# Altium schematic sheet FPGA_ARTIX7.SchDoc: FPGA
size C; Organization: Altium Limited; Address1: L3, 12a Rodborough Rd; Address2: Frenchs Forest; Address3: NSW; Address4: Australia 2086; DocumentNumber: 7; SheetNumber: 6; SheetTotal: 12
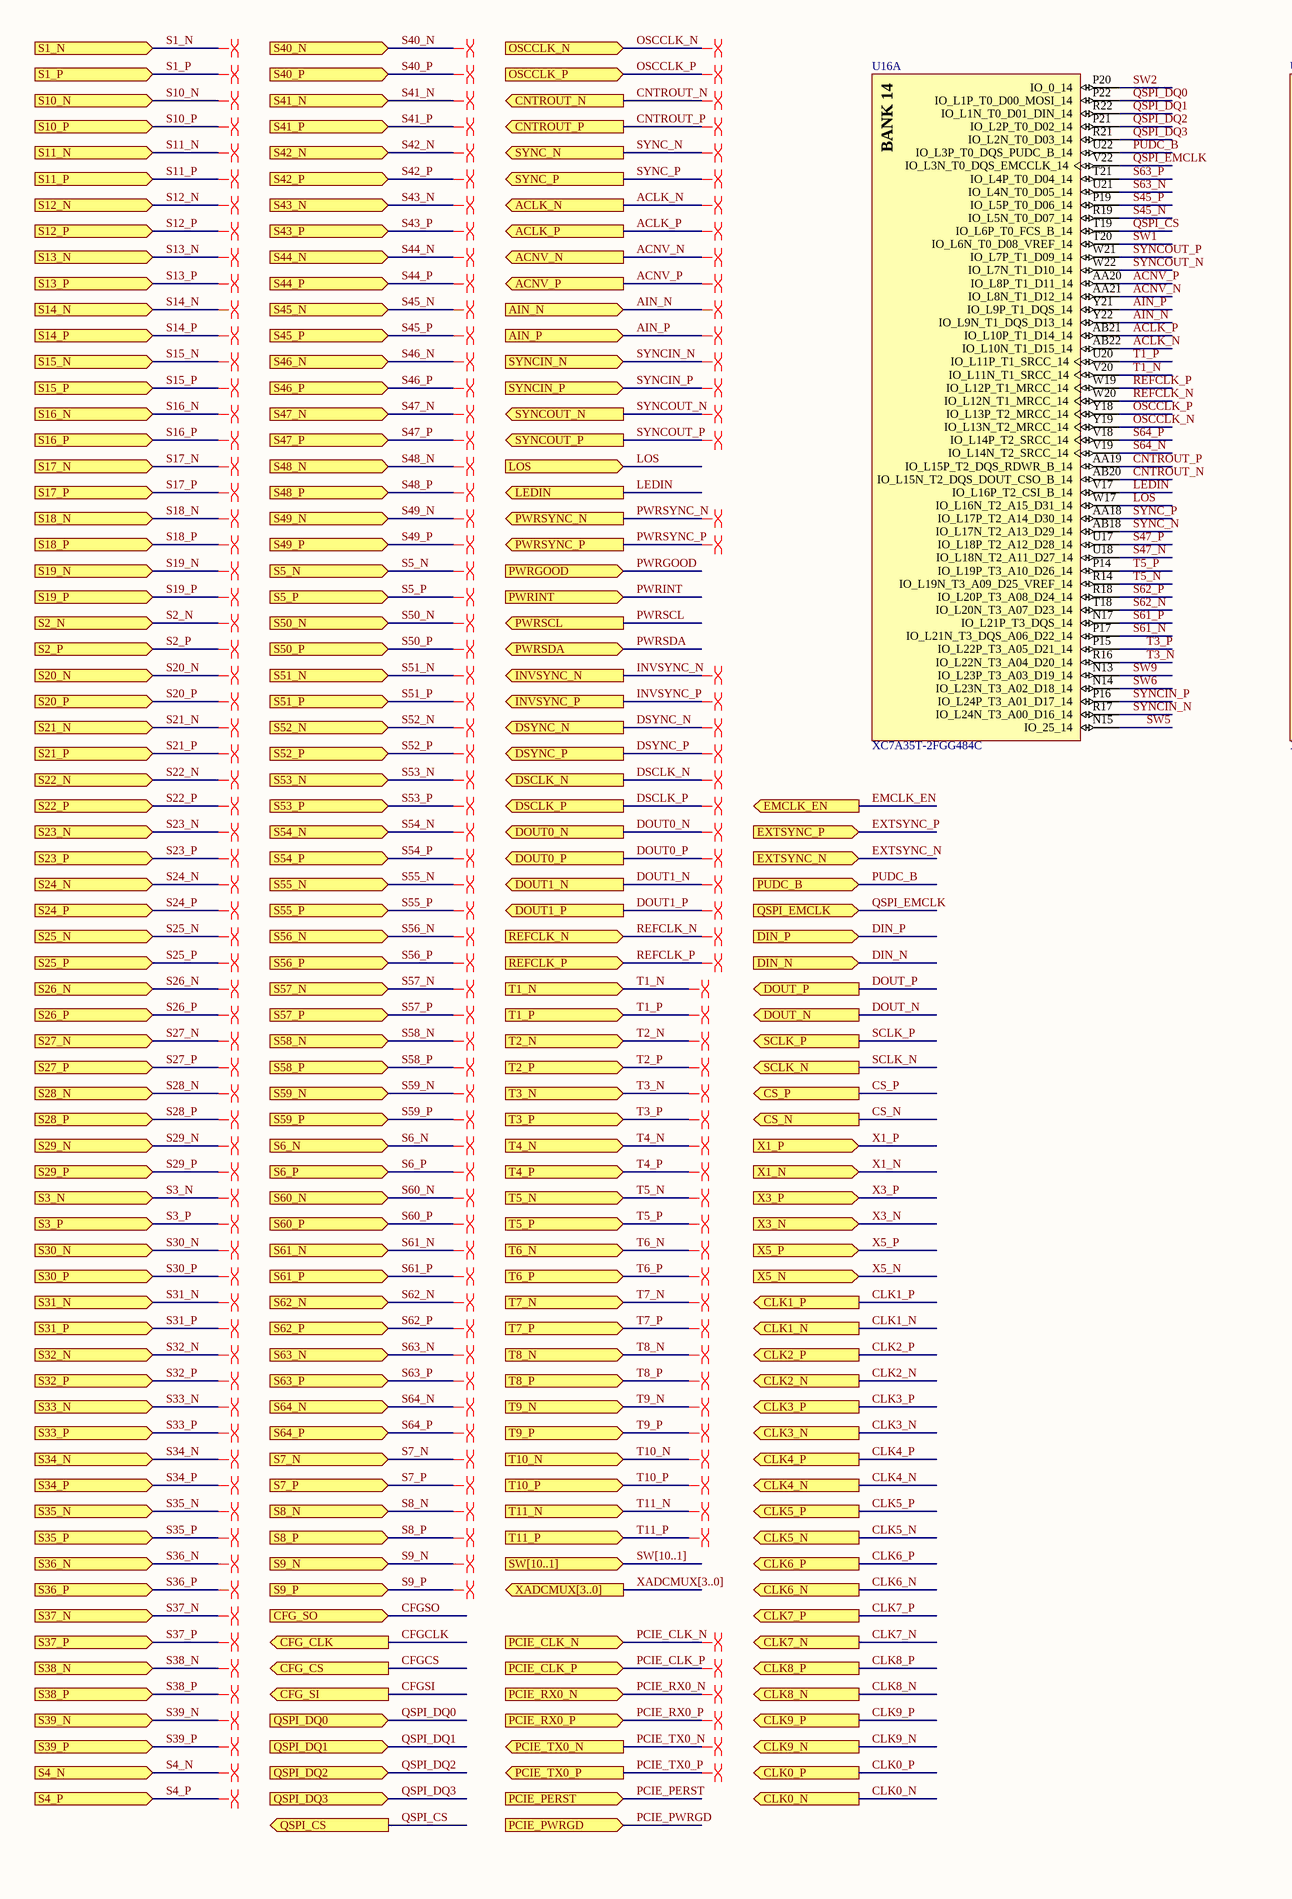
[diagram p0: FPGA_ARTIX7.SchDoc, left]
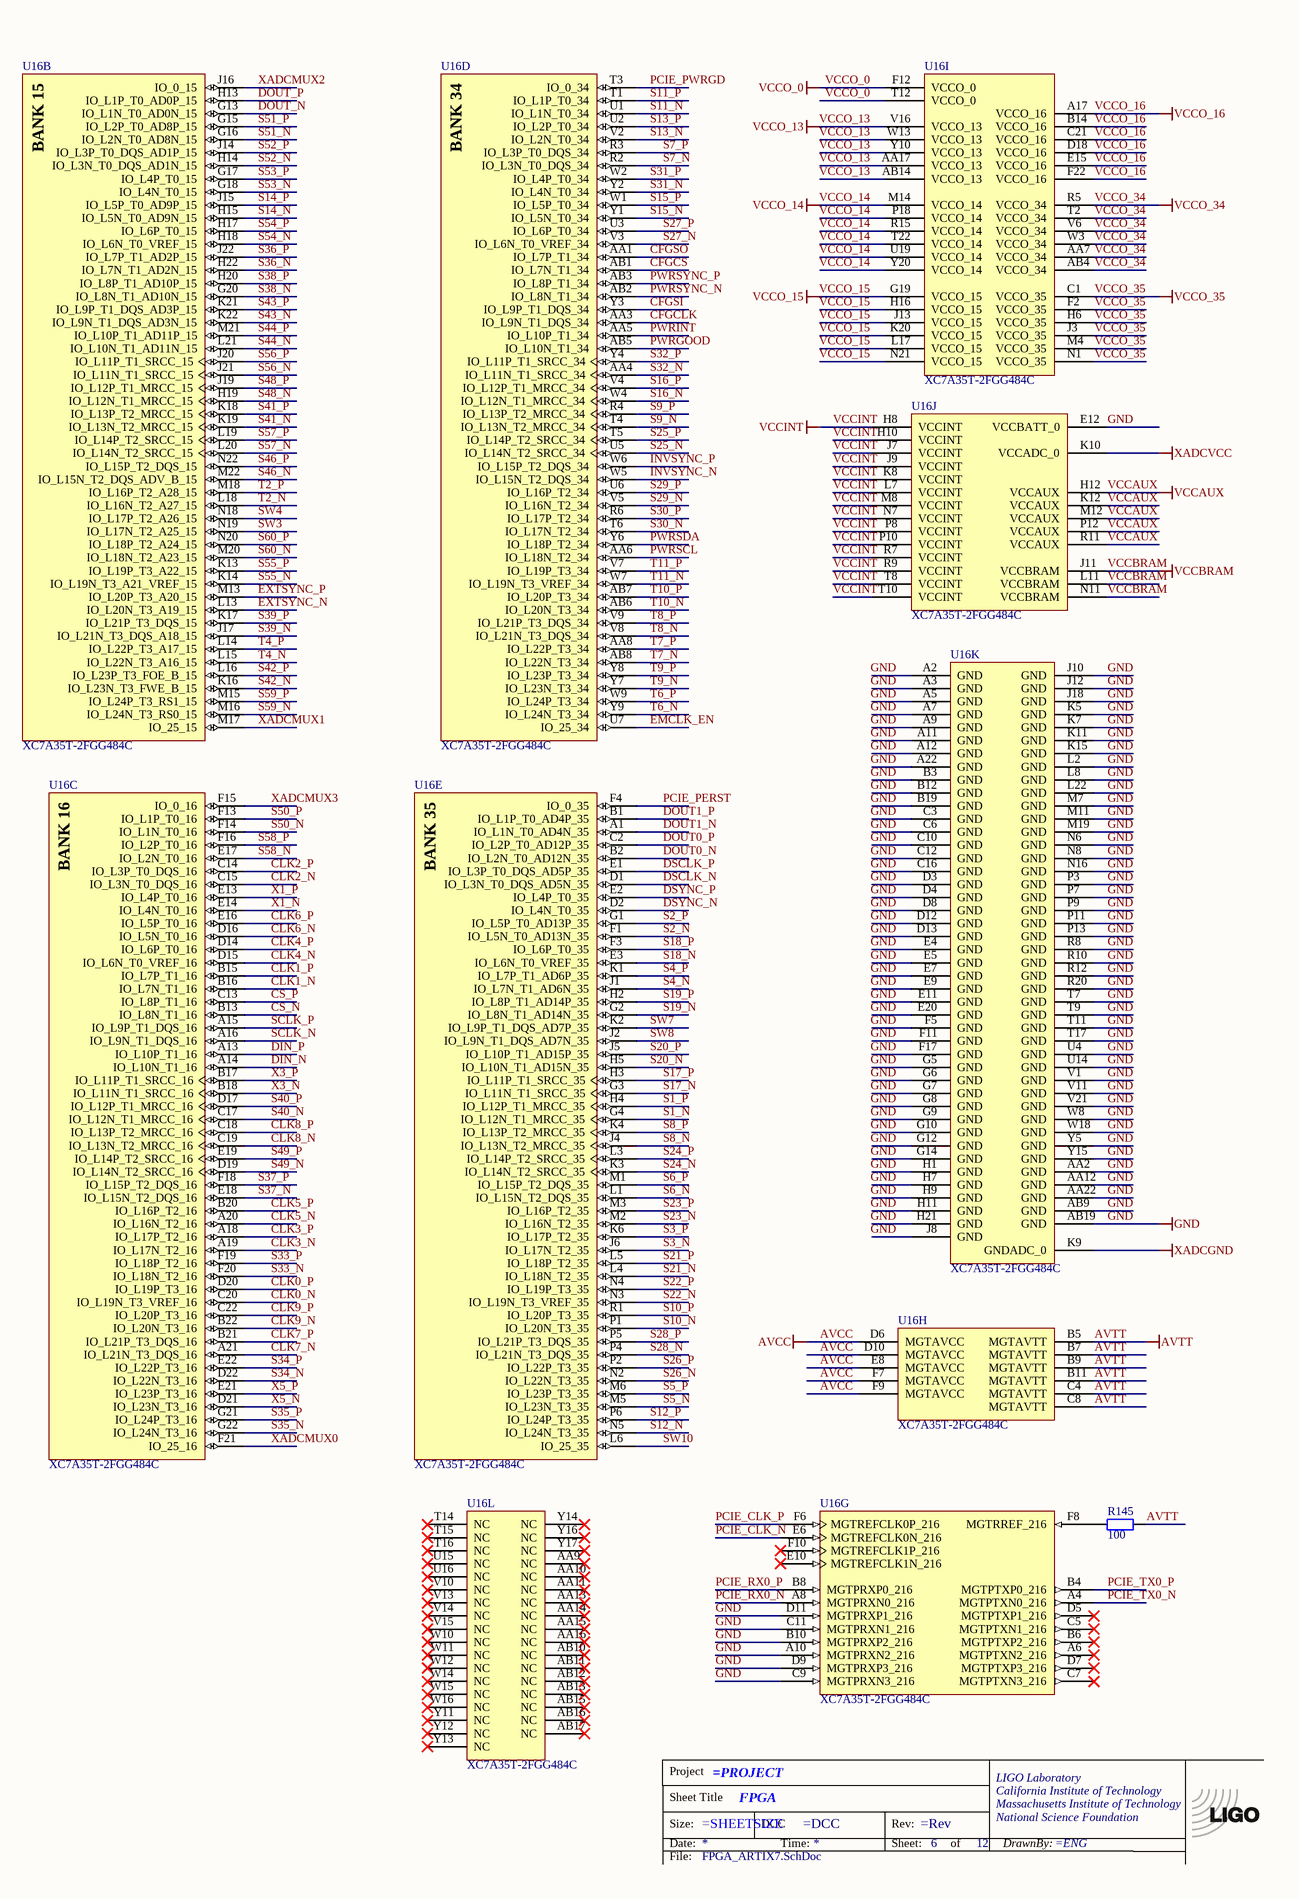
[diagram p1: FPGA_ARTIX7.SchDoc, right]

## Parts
*?  TitleBlock  (value not drawn)  (graphical)
R145  100  [CR1608-0603]
U16  XC7A35T-2FGG484C  [FGG484]  (parts A,B,C,D,E,G,H,I,J,K,L of 12)

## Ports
ACLK_N (out), ACLK_P (out), ACNV_N (out), ACNV_P (out), AIN_N (in), AIN_P (in), CFG_CLK (out), CFG_CS (out), CFG_SI (out), CFG_SO (in), CLK0_N (out), CLK0_P (out), CLK1_N (out), CLK1_P (out), CLK2_N (out), CLK2_P (out), CLK3_N (out), CLK3_P (out), CLK4_N (out), CLK4_P (out), CLK5_N (out), CLK5_P (out), CLK6_N (out), CLK6_P (out), CLK7_N (out), CLK7_P (out), CLK8_N (out), CLK8_P (out), CLK9_N (out), CLK9_P (out), CNTROUT_N (out), CNTROUT_P (out), CS_N (out), CS_P (out), DIN_N (in), DIN_P (in), DOUT0_N (out), DOUT0_P (out), DOUT1_N (out), DOUT1_P (out), DOUT_N (out), DOUT_P (out), DSCLK_N (out), DSCLK_P (out), DSYNC_N (out), DSYNC_P (out), EMCLK_EN (out), EXTSYNC_N (in), EXTSYNC_P (in), INVSYNC_N (out), INVSYNC_P (out), LEDIN (out), LOS (in), OSCCLK_N (in), OSCCLK_P (in), PCIE_CLK_N (in), PCIE_CLK_P (in), PCIE_PERST (in), PCIE_PWRGD (in), PCIE_RX0_N (in), PCIE_RX0_P (in), PCIE_TX0_N (out), PCIE_TX0_P (out), PUDC_B (in), PWRGOOD (in), PWRINT (in), PWRSCL (out), PWRSDA (bidir), PWRSYNC_N (out), PWRSYNC_P (out), QSPI_CS (out), QSPI_DQ0 (in), QSPI_DQ1 (in), QSPI_DQ2 (in), QSPI_DQ3 (in), QSPI_EMCLK (in), REFCLK_N (in), REFCLK_P (in), S1_N (in), S1_P (in), S2_N (in), S2_P (in), S3_N (in), S3_P (in), S4_N (in), S4_P (in), S5_N (in), S5_P (in), S6_N (in), S6_P (in), S7_N (in), S7_P (in), S8_N (in), S8_P (in), S9_N (in), S9_P (in), S10_N (in), S10_P (in), S11_N (in), S11_P (in), S12_N (in), S12_P (in), S13_N (in), S13_P (in), S14_N (in), S14_P (in), S15_N (in), S15_P (in), S16_N (in), S16_P (in), S17_N (in), S17_P (in), S18_N (in), S18_P (in), S19_N (in), S19_P (in), S20_N (in), S20_P (in), S21_N (in), S21_P (in), S22_N (in), S22_P (in), S23_N (in), S23_P (in), S24_N (in), S24_P (in), S25_N (in), S25_P (in), S26_N (in), S26_P (in), S27_N (in), S27_P (in), S28_N (in), S28_P (in), S29_N (in), S29_P (in), S30_N (in), S30_P (in), S31_N (in), S31_P (in), S32_N (in), S32_P (in), S33_N (in), S33_P (in), S34_N (in), S34_P (in), S35_N (in), S35_P (in), S36_N (in), S36_P (in), S37_N (in), S37_P (in), S38_N (in), S38_P (in), S39_N (in), S39_P (in), S40_N (in), S40_P (in), S41_N (in), S41_P (in), S42_N (in), S42_P (in), S43_N (in), S43_P (in), S44_N (in), S44_P (in), S45_N (in), S45_P (in), S46_N (in), S46_P (in), S47_N (in), S47_P (in), S48_N (in), S48_P (in), S49_N (in), S49_P (in), S50_N (in), S50_P (in), S51_N (in), S51_P (in), S52_N (in), S52_P (in), S53_N (in), S53_P (in), S54_N (in), S54_P (in), S55_N (in), S55_P (in), S56_N (in), S56_P (in), S57_N (in), S57_P (in), S58_N (in), S58_P (in), S59_N (in), S59_P (in), S60_N (in), S60_P (in), S61_N (in), S61_P (in), S62_N (in), S62_P (in), S63_N (in), S63_P (in), S64_N (in), S64_P (in), SCLK_N (out), SCLK_P (out), SW[10..1] (in), SYNC_N (out), SYNC_P (out), SYNCIN_N (in), SYNCIN_P (in), SYNCOUT_N (out), SYNCOUT_P (out), T1_N (in), T1_P (in), T2_N (in), T2_P (in), T3_N (in), T3_P (in), T4_N (in), T4_P (in), T5_N (in), T5_P (in), T6_N (in), T6_P (in), T7_N (in), T7_P (in), T8_N (in), T8_P (in), T9_N (in), T9_P (in), T10_N (in), T10_P (in), T11_N (in), T11_P (in), X1_N (in), X1_P (in), X3_N (in), X3_P (in), X5_N (in), X5_P (in), XADCMUX[3..0] (out)

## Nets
AVCC: U16.D6(MGTAVCC) U16.D10(MGTAVCC) U16.E8(MGTAVCC) U16.F7(MGTAVCC) U16.F9(MGTAVCC)
AVTT: R145.2 U16.B5(MGTAVTT) U16.B7(MGTAVTT) U16.B9(MGTAVTT) U16.B11(MGTAVTT) U16.C4(MGTAVTT) U16.C8(MGTAVTT)
GND: U16.A2(GND) U16.A3(GND) U16.A5(GND) U16.A7(GND) U16.A9(GND) U16.A10(MGTPRXN2_216) U16.A11(GND) U16.A12(GND) U16.A22(GND) U16.AA2(GND) U16.AA12(GND) U16.AA22(GND) U16.AB9(GND) U16.AB19(GND) U16.B3(GND) U16.B10(MGTPRXP2_216) U16.B12(GND) U16.B19(GND) U16.C3(GND) U16.C6(GND) U16.C9(MGTPRXN3_216) U16.C10(GND) U16.C11(MGTPRXN1_216) U16.C12(GND) U16.C16(GND) U16.D3(GND) U16.D4(GND) U16.D8(GND) U16.D9(MGTPRXP3_216) U16.D11(MGTPRXP1_216) U16.D12(GND) U16.D13(GND) U16.E4(GND) U16.E5(GND) U16.E7(GND) U16.E9(GND) U16.E11(GND) U16.E12(VCCBATT_0) U16.E20(GND) U16.F5(GND) U16.F11(GND) U16.F17(GND) U16.G5(GND) U16.G6(GND) U16.G7(GND) U16.G8(GND) U16.G9(GND) U16.G10(GND) U16.G12(GND) U16.G14(GND) U16.H1(GND) U16.H7(GND) U16.H9(GND) U16.H11(GND) U16.H21(GND) U16.J8(GND) U16.J10(GND) U16.J12(GND) U16.J18(GND) U16.K5(GND) U16.K7(GND) U16.K11(GND) U16.K15(GND) U16.L2(GND) U16.L8(GND) U16.L22(GND) U16.M7(GND) U16.M11(GND) U16.M19(GND) U16.N6(GND) U16.N8(GND) U16.N16(GND) U16.P3(GND) U16.P7(GND) U16.P9(GND) U16.P11(GND) U16.P13(GND) U16.R8(GND) U16.R10(GND) U16.R12(GND) U16.R20(GND) U16.T7(GND) U16.T9(GND) U16.T11(GND) U16.T17(GND) U16.U4(GND) U16.U14(GND) U16.V1(GND) U16.V11(GND) U16.V21(GND) U16.W8(GND) U16.W18(GND) U16.Y5(GND) U16.Y15(GND)
VCCAUX: U16.H12(VCCAUX) U16.K12(VCCAUX) U16.M12(VCCAUX) U16.P12(VCCAUX) U16.R11(VCCAUX)
VCCBRAM: U16.J11(VCCBRAM) U16.L11(VCCBRAM) U16.N11(VCCBRAM)
VCCINT: U16.H8(VCCINT) U16.H10(VCCINT) U16.J7(VCCINT) U16.J9(VCCINT) U16.K8(VCCINT) U16.L7(VCCINT) U16.M8(VCCINT) U16.N7(VCCINT) U16.P8(VCCINT) U16.P10(VCCINT) U16.R7(VCCINT) U16.R9(VCCINT) U16.T8(VCCINT) U16.T10(VCCINT)
VCCO_0: U16.F12(VCCO_0) U16.T12(VCCO_0)
VCCO_13: U16.AA17(VCCO_13) U16.AB14(VCCO_13) U16.V16(VCCO_13) U16.W13(VCCO_13) U16.Y10(VCCO_13)
VCCO_14: U16.M14(VCCO_14) U16.P18(VCCO_14) U16.R15(VCCO_14) U16.T22(VCCO_14) U16.U19(VCCO_14) U16.Y20(VCCO_14)
VCCO_15: U16.G19(VCCO_15) U16.H16(VCCO_15) U16.J13(VCCO_15) U16.K20(VCCO_15) U16.L17(VCCO_15) U16.N21(VCCO_15)
VCCO_16: U16.A17(VCCO_16) U16.B14(VCCO_16) U16.C21(VCCO_16) U16.D18(VCCO_16) U16.E15(VCCO_16) U16.F22(VCCO_16)
VCCO_34: U16.AA7(VCCO_34) U16.AB4(VCCO_34) U16.R5(VCCO_34) U16.T2(VCCO_34) U16.V6(VCCO_34) U16.W3(VCCO_34)
VCCO_35: U16.C1(VCCO_35) U16.F2(VCCO_35) U16.H6(VCCO_35) U16.J3(VCCO_35) U16.M4(VCCO_35) U16.N1(VCCO_35)
XADCGND: U16.K9(GNDADC_0)
XADCVCC: U16.K10(VCCADC_0)
ACLK_N: U16.AB22(IO_L10N_T1_D15_14) ; port ACLK_N
ACLK_P: U16.AB21(IO_L10P_T1_D14_14) ; port ACLK_P
ACNV_N: U16.AA21(IO_L8N_T1_D12_14) ; port ACNV_N
ACNV_P: U16.AA20(IO_L8P_T1_D11_14) ; port ACNV_P
AIN_N: U16.Y22(IO_L9N_T1_DQS_D13_14) ; port AIN_N
AIN_P: U16.Y21(IO_L9P_T1_DQS_14) ; port AIN_P
CFGCLK: U16.AA3(IO_L9N_T1_DQS_34) ; port CFG_CLK
CFGCS: U16.AB1(IO_L7N_T1_34) ; port CFG_CS
CFGSI: U16.Y3(IO_L9P_T1_DQS_34) ; port CFG_SI
CFGSO: U16.AA1(IO_L7P_T1_34) ; port CFG_SO
CLK0_N: U16.C20(IO_L19N_T3_VREF_16) ; port CLK0_N
CLK0_P: U16.D20(IO_L19P_T3_16) ; port CLK0_P
CLK1_N: U16.B16(IO_L7N_T1_16) ; port CLK1_N
CLK1_P: U16.B15(IO_L7P_T1_16) ; port CLK1_P
CLK2_N: U16.C15(IO_L3N_T0_DQS_16) ; port CLK2_N
CLK2_P: U16.C14(IO_L3P_T0_DQS_16) ; port CLK2_P
CLK3_N: U16.A19(IO_L17N_T2_16) ; port CLK3_N
CLK3_P: U16.A18(IO_L17P_T2_16) ; port CLK3_P
CLK4_N: U16.D15(IO_L6N_T0_VREF_16) ; port CLK4_N
CLK4_P: U16.D14(IO_L6P_T0_16) ; port CLK4_P
CLK5_N: U16.A20(IO_L16N_T2_16) ; port CLK5_N
CLK5_P: U16.B20(IO_L16P_T2_16) ; port CLK5_P
CLK6_N: U16.D16(IO_L5N_T0_16) ; port CLK6_N
CLK6_P: U16.E16(IO_L5P_T0_16) ; port CLK6_P
CLK7_N: U16.A21(IO_L21N_T3_DQS_16) ; port CLK7_N
CLK7_P: U16.B21(IO_L21P_T3_DQS_16) ; port CLK7_P
CLK8_N: U16.C19(IO_L13N_T2_MRCC_16) ; port CLK8_N
CLK8_P: U16.C18(IO_L13P_T2_MRCC_16) ; port CLK8_P
CLK9_N: U16.B22(IO_L20N_T3_16) ; port CLK9_N
CLK9_P: U16.C22(IO_L20P_T3_16) ; port CLK9_P
CNTROUT_N: U16.AB20(IO_L15N_T2_DQS_DOUT_CSO_B_14) ; port CNTROUT_N
CNTROUT_P: U16.AA19(IO_L15P_T2_DQS_RDWR_B_14) ; port CNTROUT_P
CS_N: U16.B13(IO_L8N_T1_16) ; port CS_N
CS_P: U16.C13(IO_L8P_T1_16) ; port CS_P
DIN_N: U16.A14(IO_L10N_T1_16) ; port DIN_N
DIN_P: U16.A13(IO_L10P_T1_16) ; port DIN_P
DOUT0_N: U16.B2(IO_L2N_T0_AD12N_35) ; port DOUT0_N
DOUT0_P: U16.C2(IO_L2P_T0_AD12P_35) ; port DOUT0_P
DOUT1_N: U16.A1(IO_L1N_T0_AD4N_35) ; port DOUT1_N
DOUT1_P: U16.B1(IO_L1P_T0_AD4P_35) ; port DOUT1_P
DOUT_N: U16.G13(IO_L1N_T0_AD0N_15) ; port DOUT_N
DOUT_P: U16.H13(IO_L1P_T0_AD0P_15) ; port DOUT_P
DSCLK_N: U16.D1(IO_L3N_T0_DQS_AD5N_35) ; port DSCLK_N
DSCLK_P: U16.E1(IO_L3P_T0_DQS_AD5P_35) ; port DSCLK_P
DSYNC_N: U16.D2(IO_L4N_T0_35) ; port DSYNC_N
DSYNC_P: U16.E2(IO_L4P_T0_35) ; port DSYNC_P
EMCLK_EN: U16.U7(IO_25_34) ; port EMCLK_EN
EXTSYNC_N: U16.L13(IO_L20N_T3_A19_15) ; port EXTSYNC_N
EXTSYNC_P: U16.M13(IO_L20P_T3_A20_15) ; port EXTSYNC_P
INVSYNC_N: U16.W5(IO_L15N_T2_DQS_34) ; port INVSYNC_N
INVSYNC_P: U16.W6(IO_L15P_T2_DQS_34) ; port INVSYNC_P
LEDIN: U16.V17(IO_L16P_T2_CSI_B_14) ; port LEDIN
LOS: U16.W17(IO_L16N_T2_A15_D31_14) ; port LOS
OSCCLK_N: U16.Y19(IO_L13N_T2_MRCC_14) ; port OSCCLK_N
OSCCLK_P: U16.Y18(IO_L13P_T2_MRCC_14) ; port OSCCLK_P
PCIE_CLK_N: U16.E6(MGTREFCLK0N_216) ; port PCIE_CLK_N
PCIE_CLK_P: U16.F6(MGTREFCLK0P_216) ; port PCIE_CLK_P
PCIE_PERST: U16.F4(IO_0_35) ; port PCIE_PERST
PCIE_PWRGD: U16.T3(IO_0_34) ; port PCIE_PWRGD
PCIE_RX0_N: U16.A8(MGTPRXN0_216) ; port PCIE_RX0_N
PCIE_RX0_P: U16.B8(MGTPRXP0_216) ; port PCIE_RX0_P
PCIE_TX0_N: U16.A4(MGTPTXN0_216) ; port PCIE_TX0_N
PCIE_TX0_P: U16.B4(MGTPTXP0_216) ; port PCIE_TX0_P
PUDC_B: U16.U22(IO_L3P_T0_DQS_PUDC_B_14) ; port PUDC_B
PWRGOOD: U16.AB5(IO_L10N_T1_34) ; port PWRGOOD
PWRINT: U16.AA5(IO_L10P_T1_34) ; port PWRINT
PWRSCL: U16.AA6(IO_L18N_T2_34) ; port PWRSCL
PWRSDA: U16.Y6(IO_L18P_T2_34) ; port PWRSDA
PWRSYNC_N: U16.AB2(IO_L8N_T1_34) ; port PWRSYNC_N
PWRSYNC_P: U16.AB3(IO_L8P_T1_34) ; port PWRSYNC_P
QSPI_CS: U16.T19(IO_L6P_T0_FCS_B_14) ; port QSPI_CS
QSPI_DQ0: U16.P22(IO_L1P_T0_D00_MOSI_14) ; port QSPI_DQ0
QSPI_DQ1: U16.R22(IO_L1N_T0_D01_DIN_14) ; port QSPI_DQ1
QSPI_DQ2: U16.P21(IO_L2P_T0_D02_14) ; port QSPI_DQ2
QSPI_DQ3: U16.R21(IO_L2N_T0_D03_14) ; port QSPI_DQ3
QSPI_EMCLK: U16.V22(IO_L3N_T0_DQS_EMCCLK_14) ; port QSPI_EMCLK
REFCLK_N: U16.W20(IO_L12N_T1_MRCC_14) ; port REFCLK_N
REFCLK_P: U16.W19(IO_L12P_T1_MRCC_14) ; port REFCLK_P
S1_N: U16.G4(IO_L12N_T1_MRCC_35) ; port S1_N
S1_P: U16.H4(IO_L12P_T1_MRCC_35) ; port S1_P
S2_N: U16.F1(IO_L5N_T0_AD13N_35) ; port S2_N
S2_P: U16.G1(IO_L5P_T0_AD13P_35) ; port S2_P
S3_N: U16.J6(IO_L17N_T2_35) ; port S3_N
S3_P: U16.K6(IO_L17P_T2_35) ; port S3_P
S4_N: U16.J1(IO_L7N_T1_AD6N_35) ; port S4_N
S4_P: U16.K1(IO_L7P_T1_AD6P_35) ; port S4_P
S5_N: U16.M5(IO_L23N_T3_35) ; port S5_N
S5_P: U16.M6(IO_L23P_T3_35) ; port S5_P
S6_N: U16.L1(IO_L15N_T2_DQS_35) ; port S6_N
S6_P: U16.M1(IO_L15P_T2_DQS_35) ; port S6_P
S7_N: U16.R2(IO_L3N_T0_DQS_34) ; port S7_N
S7_P: U16.R3(IO_L3P_T0_DQS_34) ; port S7_P
S8_N: U16.J4(IO_L13N_T2_MRCC_35) ; port S8_N
S8_P: U16.K4(IO_L13P_T2_MRCC_35) ; port S8_P
S9_N: U16.T4(IO_L13N_T2_MRCC_34) ; port S9_N
S9_P: U16.R4(IO_L13P_T2_MRCC_34) ; port S9_P
S10_N: U16.P1(IO_L20N_T3_35) ; port S10_N
S10_P: U16.R1(IO_L20P_T3_35) ; port S10_P
S11_N: U16.U1(IO_L1N_T0_34) ; port S11_N
S11_P: U16.T1(IO_L1P_T0_34) ; port S11_P
S12_N: U16.N5(IO_L24N_T3_35) ; port S12_N
S12_P: U16.P6(IO_L24P_T3_35) ; port S12_P
S13_N: U16.V2(IO_L2N_T0_34) ; port S13_N
S13_P: U16.U2(IO_L2P_T0_34) ; port S13_P
S14_N: U16.H15(IO_L5N_T0_AD9N_15) ; port S14_N
S14_P: U16.J15(IO_L5P_T0_AD9P_15) ; port S14_P
S15_N: U16.Y1(IO_L5N_T0_34) ; port S15_N
S15_P: U16.W1(IO_L5P_T0_34) ; port S15_P
S16_N: U16.W4(IO_L12N_T1_MRCC_34) ; port S16_N
S16_P: U16.V4(IO_L12P_T1_MRCC_34) ; port S16_P
S17_N: U16.G3(IO_L11N_T1_SRCC_35) ; port S17_N
S17_P: U16.H3(IO_L11P_T1_SRCC_35) ; port S17_P
S18_N: U16.E3(IO_L6N_T0_VREF_35) ; port S18_N
S18_P: U16.F3(IO_L6P_T0_35) ; port S18_P
S19_N: U16.G2(IO_L8N_T1_AD14N_35) ; port S19_N
S19_P: U16.H2(IO_L8P_T1_AD14P_35) ; port S19_P
S20_N: U16.H5(IO_L10N_T1_AD15N_35) ; port S20_N
S20_P: U16.J5(IO_L10P_T1_AD15P_35) ; port S20_P
S21_N: U16.L4(IO_L18N_T2_35) ; port S21_N
S21_P: U16.L5(IO_L18P_T2_35) ; port S21_P
S22_N: U16.N3(IO_L19N_T3_VREF_35) ; port S22_N
S22_P: U16.N4(IO_L19P_T3_35) ; port S22_P
S23_N: U16.M2(IO_L16N_T2_35) ; port S23_N
S23_P: U16.M3(IO_L16P_T2_35) ; port S23_P
S24_N: U16.K3(IO_L14N_T2_SRCC_35) ; port S24_N
S24_P: U16.L3(IO_L14P_T2_SRCC_35) ; port S24_P
S25_N: U16.U5(IO_L14N_T2_SRCC_34) ; port S25_N
S25_P: U16.T5(IO_L14P_T2_SRCC_34) ; port S25_P
S26_N: U16.N2(IO_L22N_T3_35) ; port S26_N
S26_P: U16.P2(IO_L22P_T3_35) ; port S26_P
S27_N: U16.V3(IO_L6N_T0_VREF_34) ; port S27_N
S27_P: U16.U3(IO_L6P_T0_34) ; port S27_P
S28_N: U16.P4(IO_L21N_T3_DQS_35) ; port S28_N
S28_P: U16.P5(IO_L21P_T3_DQS_35) ; port S28_P
S29_N: U16.V5(IO_L16N_T2_34) ; port S29_N
S29_P: U16.U6(IO_L16P_T2_34) ; port S29_P
S30_N: U16.T6(IO_L17N_T2_34) ; port S30_N
S30_P: U16.R6(IO_L17P_T2_34) ; port S30_P
S31_N: U16.Y2(IO_L4N_T0_34) ; port S31_N
S31_P: U16.W2(IO_L4P_T0_34) ; port S31_P
S32_N: U16.AA4(IO_L11N_T1_SRCC_34) ; port S32_N
S32_P: U16.Y4(IO_L11P_T1_SRCC_34) ; port S32_P
S33_N: U16.F20(IO_L18N_T2_16) ; port S33_N
S33_P: U16.F19(IO_L18P_T2_16) ; port S33_P
S34_N: U16.D22(IO_L22N_T3_16) ; port S34_N
S34_P: U16.E22(IO_L22P_T3_16) ; port S34_P
S35_N: U16.G22(IO_L24N_T3_16) ; port S35_N
S35_P: U16.G21(IO_L24P_T3_16) ; port S35_P
S36_N: U16.H22(IO_L7N_T1_AD2N_15) ; port S36_N
S36_P: U16.J22(IO_L7P_T1_AD2P_15) ; port S36_P
S37_N: U16.E18(IO_L15N_T2_DQS_16) ; port S37_N
S37_P: U16.F18(IO_L15P_T2_DQS_16) ; port S37_P
S38_N: U16.G20(IO_L8N_T1_AD10N_15) ; port S38_N
S38_P: U16.H20(IO_L8P_T1_AD10P_15) ; port S38_P
S39_N: U16.J17(IO_L21N_T3_DQS_A18_15) ; port S39_N
S39_P: U16.K17(IO_L21P_T3_DQS_15) ; port S39_P
S40_N: U16.C17(IO_L12N_T1_MRCC_16) ; port S40_N
S40_P: U16.D17(IO_L12P_T1_MRCC_16) ; port S40_P
S41_N: U16.K19(IO_L13N_T2_MRCC_15) ; port S41_N
S41_P: U16.K18(IO_L13P_T2_MRCC_15) ; port S41_P
S42_N: U16.K16(IO_L23N_T3_FWE_B_15) ; port S42_N
S42_P: U16.L16(IO_L23P_T3_FOE_B_15) ; port S42_P
S43_N: U16.K22(IO_L9N_T1_DQS_AD3N_15) ; port S43_N
S43_P: U16.K21(IO_L9P_T1_DQS_AD3P_15) ; port S43_P
S44_N: U16.L21(IO_L10N_T1_AD11N_15) ; port S44_N
S44_P: U16.M21(IO_L10P_T1_AD11P_15) ; port S44_P
S45_N: U16.R19(IO_L5N_T0_D07_14) ; port S45_N
S45_P: U16.P19(IO_L5P_T0_D06_14) ; port S45_P
S46_N: U16.M22(IO_L15N_T2_DQS_ADV_B_15) ; port S46_N
S46_P: U16.N22(IO_L15P_T2_DQS_15) ; port S46_P
S47_N: U16.U18(IO_L18N_T2_A11_D27_14) ; port S47_N
S47_P: U16.U17(IO_L18P_T2_A12_D28_14) ; port S47_P
S48_N: U16.H19(IO_L12N_T1_MRCC_15) ; port S48_N
S48_P: U16.J19(IO_L12P_T1_MRCC_15) ; port S48_P
S49_N: U16.D19(IO_L14N_T2_SRCC_16) ; port S49_N
S49_P: U16.E19(IO_L14P_T2_SRCC_16) ; port S49_P
S50_N: U16.F14(IO_L1N_T0_16) ; port S50_N
S50_P: U16.F13(IO_L1P_T0_16) ; port S50_P
S51_N: U16.G16(IO_L2N_T0_AD8N_15) ; port S51_N
S51_P: U16.G15(IO_L2P_T0_AD8P_15) ; port S51_P
S52_N: U16.H14(IO_L3N_T0_DQS_AD1N_15) ; port S52_N
S52_P: U16.J14(IO_L3P_T0_DQS_AD1P_15) ; port S52_P
S53_N: U16.G18(IO_L4N_T0_15) ; port S53_N
S53_P: U16.G17(IO_L4P_T0_15) ; port S53_P
S54_N: U16.H18(IO_L6N_T0_VREF_15) ; port S54_N
S54_P: U16.H17(IO_L6P_T0_15) ; port S54_P
S55_N: U16.K14(IO_L19N_T3_A21_VREF_15) ; port S55_N
S55_P: U16.K13(IO_L19P_T3_A22_15) ; port S55_P
S56_N: U16.J21(IO_L11N_T1_SRCC_15) ; port S56_N
S56_P: U16.J20(IO_L11P_T1_SRCC_15) ; port S56_P
S57_N: U16.L20(IO_L14N_T2_SRCC_15) ; port S57_N
S57_P: U16.L19(IO_L14P_T2_SRCC_15) ; port S57_P
S58_N: U16.E17(IO_L2N_T0_16) ; port S58_N
S58_P: U16.F16(IO_L2P_T0_16) ; port S58_P
S59_N: U16.M16(IO_L24N_T3_RS0_15) ; port S59_N
S59_P: U16.M15(IO_L24P_T3_RS1_15) ; port S59_P
S60_N: U16.M20(IO_L18N_T2_A23_15) ; port S60_N
S60_P: U16.N20(IO_L18P_T2_A24_15) ; port S60_P
S61_N: U16.P17(IO_L21N_T3_DQS_A06_D22_14) ; port S61_N
S61_P: U16.N17(IO_L21P_T3_DQS_14) ; port S61_P
S62_N: U16.T18(IO_L20N_T3_A07_D23_14) ; port S62_N
S62_P: U16.R18(IO_L20P_T3_A08_D24_14) ; port S62_P
S63_N: U16.U21(IO_L4N_T0_D05_14) ; port S63_N
S63_P: U16.T21(IO_L4P_T0_D04_14) ; port S63_P
S64_N: U16.V19(IO_L14N_T2_SRCC_14) ; port S64_N
S64_P: U16.V18(IO_L14P_T2_SRCC_14) ; port S64_P
SCLK_N: U16.A16(IO_L9N_T1_DQS_16) ; port SCLK_N
SCLK_P: U16.A15(IO_L9P_T1_DQS_16) ; port SCLK_P
SW1: U16.T20(IO_L6N_T0_D08_VREF_14)
SW2: U16.P20(IO_0_14)
SW3: U16.N19(IO_L17N_T2_A25_15)
SW4: U16.N18(IO_L17P_T2_A26_15)
SW5: U16.N15(IO_25_14)
SW6: U16.N14(IO_L23N_T3_A02_D18_14)
SW7: U16.K2(IO_L9P_T1_DQS_AD7P_35)
SW8: U16.J2(IO_L9N_T1_DQS_AD7N_35)
SW9: U16.N13(IO_L23P_T3_A03_D19_14)
SW10: U16.L6(IO_25_35)
SYNC_N: U16.AB18(IO_L17N_T2_A13_D29_14) ; port SYNC_N
SYNC_P: U16.AA18(IO_L17P_T2_A14_D30_14) ; port SYNC_P
SYNCIN_N: U16.R17(IO_L24N_T3_A00_D16_14) ; port SYNCIN_N
SYNCIN_P: U16.P16(IO_L24P_T3_A01_D17_14) ; port SYNCIN_P
SYNCOUT_N: U16.W22(IO_L7N_T1_D10_14) ; port SYNCOUT_N
SYNCOUT_P: U16.W21(IO_L7P_T1_D09_14) ; port SYNCOUT_P
T1_N: U16.V20(IO_L11N_T1_SRCC_14) ; port T1_N
T1_P: U16.U20(IO_L11P_T1_SRCC_14) ; port T1_P
T2_N: U16.L18(IO_L16N_T2_A27_15) ; port T2_N
T2_P: U16.M18(IO_L16P_T2_A28_15) ; port T2_P
T3_N: U16.R16(IO_L22N_T3_A04_D20_14) ; port T3_N
T3_P: U16.P15(IO_L22P_T3_A05_D21_14) ; port T3_P
T4_N: U16.L15(IO_L22N_T3_A16_15) ; port T4_N
T4_P: U16.L14(IO_L22P_T3_A17_15) ; port T4_P
T5_N: U16.R14(IO_L19N_T3_A09_D25_VREF_14) ; port T5_N
T5_P: U16.P14(IO_L19P_T3_A10_D26_14) ; port T5_P
T6_N: U16.Y9(IO_L24N_T3_34) ; port T6_N
T6_P: U16.W9(IO_L24P_T3_34) ; port T6_P
T7_N: U16.AB8(IO_L22N_T3_34) ; port T7_N
T7_P: U16.AA8(IO_L22P_T3_34) ; port T7_P
T8_N: U16.V8(IO_L21N_T3_DQS_34) ; port T8_N
T8_P: U16.V9(IO_L21P_T3_DQS_34) ; port T8_P
T9_N: U16.Y7(IO_L23N_T3_34) ; port T9_N
T9_P: U16.Y8(IO_L23P_T3_34) ; port T9_P
T10_N: U16.AB6(IO_L20N_T3_34) ; port T10_N
T10_P: U16.AB7(IO_L20P_T3_34) ; port T10_P
T11_N: U16.W7(IO_L19N_T3_VREF_34) ; port T11_N
T11_P: U16.V7(IO_L19P_T3_34) ; port T11_P
X1_N: U16.E14(IO_L4N_T0_16) ; port X1_N
X1_P: U16.E13(IO_L4P_T0_16) ; port X1_P
X3_N: U16.B18(IO_L11N_T1_SRCC_16) ; port X3_N
X3_P: U16.B17(IO_L11P_T1_SRCC_16) ; port X3_P
X5_N: U16.D21(IO_L23N_T3_16) ; port X5_N
X5_P: U16.E21(IO_L23P_T3_16) ; port X5_P
XADCMUX0: U16.F21(IO_25_16)
XADCMUX1: U16.M17(IO_25_15)
XADCMUX2: U16.J16(IO_0_15)
XADCMUX3: U16.F15(IO_0_16)
NetR145_1: R145.1 U16.F8(MGTRREF_216)

Not connected (* = marked no-connect by the designer): U16 A6(MGTPTXN2_216)* AA9(NC)* AA10(NC)* AA11(NC)* AA13(NC)* AA14(NC)* AA15(NC)* AA16(NC)* AB10(NC)* AB11(NC)* AB12(NC)* AB13(NC)* AB15(NC)* AB16(NC)* AB17(NC)* B6(MGTPTXP2_216)* C5(MGTPTXN1_216)* C7(MGTPTXN3_216)* D5(MGTPTXP1_216)* D7(MGTPTXP3_216)* E10(MGTREFCLK1N_216)* F10(MGTREFCLK1P_216)* T14(NC)* T15(NC)* T16(NC)* U15(NC)* U16(NC)* V10(NC)* V13(NC)* V14(NC)* V15(NC)* W10(NC)* W11(NC)* W12(NC)* W14(NC)* W15(NC)* W16(NC)* Y11(NC)* Y12(NC)* Y13(NC)* Y14(NC)* Y16(NC)* Y17(NC)*

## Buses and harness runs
bus SW[10..1] = port SW[10..1]
bus XADCMUX[3..0] = port XADCMUX[3..0]

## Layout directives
differential pair: ACLK_N, ACLK_P, ACNV_N, ACNV_P, AIN_N, AIN_P, CNTROUT_N, CNTROUT_P, DOUT0_N, DOUT0_P, DOUT1_N, DOUT1_P, DSCLK_N, DSCLK_P, DSYNC_N, DSYNC_P, INVSYNC_N, INVSYNC_P, OSCCLK_N, OSCCLK_P, PCIE_CLK_N, PCIE_CLK_P, PCIE_RX0_N, PCIE_RX0_P, PCIE_TX0_N, PCIE_TX0_P, PWRSYNC_N, PWRSYNC_P, REFCLK_N, REFCLK_P, S1_N, S1_P, S2_N, S2_P, S3_N, S3_P, S4_N, S4_P, S5_N, S5_P, S6_N, S6_P, S7_N, S7_P, S8_N, S8_P, S9_N, S9_P, S10_N, S10_P, S11_N, S11_P, S12_N, S12_P, S13_N, S13_P, S14_N, S14_P, S15_N, S15_P, S16_N, S16_P, S17_N, S17_P, S18_N, S18_P, S19_N, S19_P, S20_N, S20_P, S21_N, S21_P, S22_N, S22_P, S23_N, S23_P, S24_N, S24_P, S25_N, S25_P, S26_N, S26_P, S27_N, S27_P, S28_N, S28_P, S29_N, S29_P, S30_N, S30_P, S31_N, S31_P, S32_N, S32_P, S33_N, S33_P, S34_N, S34_P, S35_N, S35_P, S36_N, S36_P, S37_N, S37_P, S38_N, S38_P, S39_N, S39_P, S40_N, S40_P, S41_N, S41_P, S42_N, S42_P, S43_N, S43_P, S44_N, S44_P, S45_N, S45_P, S46_N, S46_P, S47_N, S47_P, S48_N, S48_P, S49_N, S49_P, S50_N, S50_P, S51_N, S51_P, S52_N, S52_P, S53_N, S53_P, S54_N, S54_P, S55_N, S55_P, S56_N, S56_P, S57_N, S57_P, S58_N, S58_P, S59_N, S59_P, S60_N, S60_P, S61_N, S61_P, S62_N, S62_P, S63_N, S63_P, S64_N, S64_P, SYNC_N, SYNC_P, SYNCIN_N, SYNCIN_P, SYNCOUT_N, SYNCOUT_P, T1_N, T1_P, T2_N, T2_P, T3_N, T3_P, T4_N, T4_P, T5_N, T5_P, T6_N, T6_P, T7_N, T7_P, T8_N, T8_P, T9_N, T9_P, T10_N, T10_P, T11_N, T11_P

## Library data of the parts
R145 = ChipRes1: R0603 100; Part Number: RR08P100DCT-ND; Tolerance: 0.1%
U16 = CMP-0383-00019-1: Artix-7 FPGA, 250 User I/Os, 4 GTP, 484-Ball BGA, Speed Grade 2, Commercial Grade, Pb-Free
